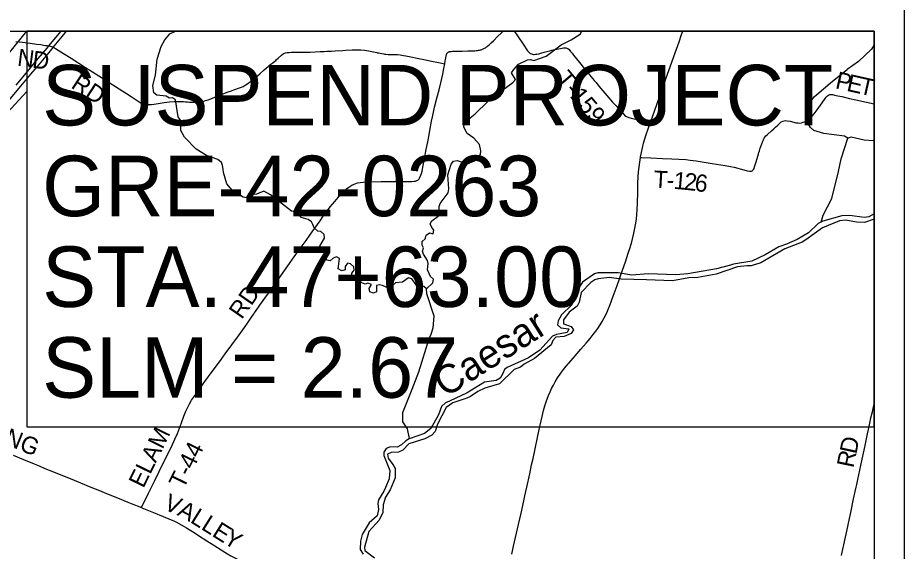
# Model space of a CAD drawing. Extents: x -19.5 to 44.1, y 0 to 22.
# Drawn here: x 6.569 to 9.5, y 16.078 to 17.841 of the extents above; entities that cross this region are included whole.
import ezdxf

# ---------------------------------------------------------------- set-up
doc = ezdxf.new("R2010")
doc.units = 0
for name, color, linetype in [('GM_X_County_Road', 7, 'Continuous'), ('GM_X_County_Road_Text', 7, 'Continuous'), ('GM_X_Major_River', 7, 'Continuous'), ('GM_X_Major_River_Text', 7, 'Continuous'), ('GM_X_Minor_River', 7, 'Continuous'), ('GM_X_State_Route', 7, 'Continuous'), ('GM_X_Township_Road', 7, 'Continuous'), ('GM_X_Township_Road_Text', 7, 'Continuous'), ('GM_X_US_Route', 7, 'Continuous'), ('SH_Data', 7, 'Continuous'), ('SH_Masking', 7, 'Continuous'), ('SH_Text', 7, 'Continuous')]:
    doc.layers.add(name, color=color, linetype=linetype)

msp = doc.modelspace()

# ---------------------------------------------------------------- linework, layer by layer
at = {"layer": 'GM_X_County_Road'}
for points in [[(9.292, 16.0637), (9.2979, 16.0906), (9.2999, 16.0997), (9.3053, 16.1246), (9.3096, 16.1447), (9.3185, 16.186), (9.3228, 16.2066), (9.3325, 16.2516), (9.3378, 16.2752), (9.3409, 16.2898), (9.3427, 16.2983), (9.3462, 16.3147), (9.3496, 16.3305), (9.3531, 16.3462), (9.3611, 16.382), (9.3652, 16.4027), (9.3704, 16.4277), (9.3787, 16.4665), (9.3816, 16.4805), (9.3862, 16.5017), (9.3899, 16.5186), (9.3945, 16.5393), (9.3981, 16.5548), (9.4, 16.5632)], [(6.5534, 16.3958), (6.5878, 16.3814), (6.6229, 16.3671), (6.6395, 16.3601), (6.659, 16.352), (6.6815, 16.343), (6.6948, 16.3377), (6.731, 16.3228), (6.7552, 16.3132), (6.8103, 16.2903), (6.8396, 16.2784), (6.862, 16.2692), (6.904, 16.2522), (6.927, 16.2429), (6.9316, 16.2411), (6.9333, 16.2404), (6.9441, 16.236), (6.978, 16.2221)], [(6.978, 16.2221), (6.9792, 16.2216), (7.0178, 16.206), (7.0504, 16.1923), (7.0871, 16.1771), (7.0944, 16.1737), (7.1016, 16.1701), (7.1118, 16.1643), (7.1266, 16.1552), (7.1356, 16.1497), (7.1519, 16.1395), (7.1672, 16.1299), (7.1938, 16.1128), (7.2086, 16.1037), (7.2291, 16.0908), (7.2542, 16.0747), (7.2622, 16.0698), (7.2741, 16.0631), (7.2867, 16.0563), (7.2996, 16.05), (7.311, 16.045), (7.3237, 16.0398), (7.3281, 16.0383)]]:
    msp.add_lwpolyline(points, dxfattribs=at)
at = {"layer": 'GM_X_Major_River'}
for points in [[(9.4, 17.1929), (9.3828, 17.183), (9.3672, 17.1807), (9.3202, 17.1875), (9.294, 17.1869), (9.2308, 17.169), (9.2158, 17.161), (9.1836, 17.1306), (9.1462, 17.1083), (9.1105, 17.0931), (9.0852, 17.0838), (9.0401, 17.0579), (8.9959, 17.0372), (8.9352, 17.0269), (8.9257, 17.024), (8.8794, 17.0114), (8.7843, 16.995), (8.7451, 16.9913), (8.6528, 16.9946), (8.5995, 16.9905), (8.554, 16.998), (8.4871, 16.9984)], [(9.4, 17.1756), (9.3684, 17.1647), (9.3418, 17.1661), (9.3066, 17.1722), (9.2864, 17.1696), (9.2296, 17.1474), (9.1751, 17.1076), (9.1619, 17.0991), (9.1048, 17.0773), (9.0262, 17.0308), (8.9933, 17.0217), (8.9792, 17.0213), (8.9491, 17.0182), (8.8782, 16.994), (8.8175, 16.9832), (8.7874, 16.9812), (8.734, 16.9722), (8.6478, 16.9746), (8.5638, 16.9777), (8.524, 16.9828), (8.4882, 16.9787)], [(8.4871, 16.9984), (8.4764, 16.9945), (8.4362, 16.9669), (8.411, 16.9295), (8.4059, 16.9057), (8.4007, 16.8921), (8.3665, 16.8598), (8.3561, 16.8395), (8.3535, 16.8263), (8.3647, 16.8165), (8.3905, 16.8129), (8.3853, 16.8005), (8.3502, 16.7948), (8.3367, 16.7894), (8.295, 16.7425), (8.2575, 16.7168), (8.1876, 16.6849), (8.1779, 16.6787), (8.1731, 16.6659), (8.164, 16.6505), (8.1509, 16.6428), (8.112, 16.6369), (8.0545, 16.6013), (7.9969, 16.5738), (7.9838, 16.5684), (7.9702, 16.5569), (7.9605, 16.529), (7.9351, 16.4832), (7.9142, 16.4674), (7.8628, 16.4499), (7.8517, 16.443), (7.838, 16.4292), (7.8234, 16.4219), (7.801, 16.4236), (7.7876, 16.4171), (7.7789, 16.4051), (7.7794, 16.3941), (7.7996, 16.3446), (7.7967, 16.3177), (7.785, 16.2883), (7.7794, 16.2762), (7.7613, 16.2482), (7.7591, 16.2353), (7.7616, 16.2158), (7.7574, 16.1947), (7.7306, 16.1721), (7.7081, 16.1338), (7.7026, 16.1112), (7.7016, 16.0842), (7.7107, 16.0684)], [(8.4882, 16.9787), (8.4767, 16.9751), (8.4643, 16.9659), (8.432, 16.9332), (8.4252, 16.901), (8.4185, 16.8883), (8.3925, 16.868), (8.3737, 16.8433), (8.373, 16.8293), (8.399, 16.8211), (8.4068, 16.8099), (8.3989, 16.7975), (8.3755, 16.7882), (8.3484, 16.7858), (8.3379, 16.7746), (8.3326, 16.7603), (8.2772, 16.7152), (8.2437, 16.6962), (8.2317, 16.6866), (8.2099, 16.6787), (8.1616, 16.6308), (8.1134, 16.6167), (8.09, 16.6058), (8.0664, 16.5897), (8.0534, 16.5843), (8.007, 16.5682), (7.9854, 16.5531), (7.9567, 16.4983), (7.9486, 16.4742), (7.9376, 16.4615), (7.9145, 16.4491), (7.8625, 16.4328), (7.8418, 16.412), (7.8284, 16.4059), (7.8033, 16.4045), (7.7913, 16.3984), (7.7933, 16.3858), (7.8096, 16.3649), (7.8165, 16.351), (7.8165, 16.3202), (7.8004, 16.2807), (7.7846, 16.2564), (7.7772, 16.2311), (7.7766, 16.206), (7.7639, 16.1804), (7.73, 16.1436), (7.7151, 16.0919), (7.7163, 16.0801), (7.7488, 16.0557)]]:
    msp.add_lwpolyline(points, dxfattribs=at)
at = {"layer": 'GM_X_Minor_River'}
for points in [[(7.0298, 17.7049), (7.0436, 17.7467), (7.055, 17.7678), (7.0721, 17.7884), (7.0904, 17.7973)], [(8.2246, 17.6874), (8.2541, 17.7017), (8.2644, 17.7034), (8.2753, 17.7005), (8.3162, 17.7147), (8.3658, 17.7518), (8.3988, 17.7683), (8.4283, 17.7875), (8.4345, 17.7973)], [(9.4, 17.7521), (9.3919, 17.7375), (9.3483, 17.6965), (9.311, 17.6705)], [(7.9208, 16.9457), (7.9111, 16.9535), (7.8865, 16.9586), (7.8722, 16.9787), (7.8608, 16.9816), (7.8408, 16.9669), (7.8184, 16.9648), (7.7967, 16.9463), (7.7753, 16.9567), (7.7647, 16.9588), (7.7552, 16.956), (7.7547, 16.9351), (7.7452, 16.9308), (7.7335, 16.9356), (7.7311, 16.9463), (7.7382, 16.9598), (7.7269, 16.9643), (7.7173, 16.9603), (7.7068, 16.9647), (7.6957, 16.9764), (7.6739, 16.9868), (7.6737, 16.9974), (7.6808, 17.0071), (7.6802, 17.0178), (7.6694, 17.0275), (7.6596, 17.03), (7.6514, 17.0188), (7.652, 17.0086), (7.6405, 17.0046), (7.6281, 17.011), (7.633, 17.0451), (7.6229, 17.051), (7.6118, 17.0467), (7.6017, 17.0375), (7.5915, 17.0396), (7.5884, 17.0503), (7.5985, 17.0618), (7.6002, 17.0717), (7.5896, 17.0738), (7.5747, 17.0689), (7.5649, 17.071), (7.5647, 17.0809), (7.5832, 17.1127), (7.582, 17.1245), (7.5716, 17.135), (7.561, 17.136), (7.5494, 17.1466), (7.5447, 17.1577), (7.5408, 17.1673), (7.5292, 17.1748), (7.5065, 17.1814), (7.4849, 17.1994), (7.4736, 17.2023), (7.4049, 17.2559), (7.3824, 17.2678), (7.3579, 17.2578), (7.3473, 17.2573), (7.3258, 17.246), (7.3141, 17.2482), (7.2778, 17.2714), (7.26, 17.2927), (7.249, 17.3295), (7.2485, 17.3409), (7.2465, 17.3527), (7.2425, 17.3634), (7.2302, 17.3724), (7.1929, 17.3858), (7.1592, 17.4064), (7.1206, 17.4468), (7.1078, 17.4684), (7.1074, 17.5026), (7.0993, 17.5142), (7.0906, 17.5698), (7.0809, 17.5769), (7.071, 17.5752), (7.0594, 17.5823), (7.0287, 17.5853), (7.019, 17.5935), (7.0154, 17.6172), (7.0248, 17.6511), (7.0298, 17.7049)], [(7.8648, 16.4506), (7.8574, 16.4826), (7.8427, 16.5053), (7.8426, 16.5369), (7.8735, 16.6132), (7.8952, 16.6705), (7.929, 16.7817), (7.9358, 16.796), (7.9423, 16.8164), (7.9458, 16.8551), (7.922, 16.9293), (7.9208, 16.9457), (7.9409, 16.9653), (7.9439, 16.977), (7.9334, 16.9864), (7.924, 17.0079), (7.9256, 17.0291), (7.9236, 17.0394), (7.9107, 17.0599), (7.9075, 17.0702), (7.91, 17.0804), (7.9057, 17.09), (7.9063, 17.1021), (7.9163, 17.1103), (7.9193, 17.1231), (7.9301, 17.1308), (7.9421, 17.1271), (7.945, 17.1392), (7.9365, 17.1497), (7.933, 17.16), (7.9381, 17.1698), (7.9586, 17.1852), (7.9637, 17.1965), (7.9627, 17.2174), (7.9655, 17.2272), (7.9921, 17.2631), (7.9943, 17.276), (7.9907, 17.3216), (8.0017, 17.3578), (8.0099, 17.3675), (8.0217, 17.3691), (8.0556, 17.3585), (8.0786, 17.3686), (8.0898, 17.3767), (8.0992, 17.3897), (8.1005, 17.4015), (8.0957, 17.4221), (8.0768, 17.4431), (8.0551, 17.4588), (8.0434, 17.4796), (8.0455, 17.4901), (8.0541, 17.5017), (8.0819, 17.5235), (8.0908, 17.5331), (8.1358, 17.5758), (8.2059, 17.6273), (8.2145, 17.6374), (8.2013, 17.6597), (8.2091, 17.6698), (8.2246, 17.6874)], [(9.3139, 17.4434), (9.3029, 17.4497), (9.2344, 17.4585), (9.2013, 17.4688), (9.1905, 17.4785), (9.1839, 17.4901), (9.1821, 17.5137), (9.1947, 17.57), (9.2029, 17.5812), (9.2628, 17.6314), (9.311, 17.6705)], [(9.2257, 17.1662), (9.2321, 17.1884), (9.2602, 17.244), (9.2826, 17.3331), (9.2911, 17.3755), (9.3138, 17.4433), (9.3242, 17.4476), (9.3676, 17.4375), (9.3971, 17.4357), (9.4, 17.4367)]]:
    msp.add_lwpolyline(points, dxfattribs=at)
at = {"layer": 'GM_X_State_Route'}
for points in [[(8.6623, 17.4986), (8.6691, 17.5175), (8.6953, 17.592), (8.7042, 17.6178), (8.7128, 17.6424), (8.7214, 17.667), (8.7423, 17.7248), (8.7557, 17.7622), (8.7639, 17.7856), (8.7676, 17.7973)], [(8.2952, 16.4899), (8.2962, 16.4946), (8.3029, 16.5237), (8.3078, 16.543), (8.3122, 16.5585), (8.3165, 16.5722), (8.3205, 16.584), (8.3241, 16.5933), (8.329, 16.6047), (8.3342, 16.616), (8.3399, 16.6272), (8.3456, 16.6375), (8.3538, 16.6507), (8.362, 16.6633), (8.367, 16.6704), (8.3731, 16.6783), (8.3825, 16.6899), (8.406, 16.7173), (8.431, 16.7458), (8.4486, 16.7658), (8.4618, 16.7815), (8.4719, 16.7941), (8.4801, 16.805), (8.4868, 16.8146), (8.4943, 16.826), (8.5014, 16.8377), (8.508, 16.8496), (8.514, 16.8612), (8.5187, 16.8713), (8.5224, 16.8798), (8.5278, 16.8937), (8.5379, 16.9211), (8.5503, 16.9562), (8.5592, 16.9814), (8.5684, 17.0072), (8.5779, 17.0348), (8.5876, 17.0629), (8.5937, 17.0819), (8.5992, 17.1009), (8.6029, 17.1153), (8.6061, 17.1292), (8.6095, 17.1463), (8.6123, 17.1628), (8.6142, 17.1769), (8.6157, 17.1911), (8.6168, 17.2066), (8.6178, 17.2289), (8.6189, 17.2649), (8.6196, 17.2947), (8.6205, 17.3153), (8.6218, 17.332), (8.6233, 17.3475), (8.6255, 17.3641), (8.6279, 17.3798), (8.6281, 17.3814), (8.6308, 17.3954), (8.6343, 17.4112), (8.6381, 17.4263), (8.6422, 17.4407), (8.647, 17.4555), (8.6546, 17.4772), (8.6613, 17.4957), (8.6623, 17.4986)], [(8.2027, 16.068), (8.2086, 16.0947), (8.2212, 16.1517), (8.2245, 16.1669), (8.2331, 16.2044), (8.2422, 16.245), (8.2458, 16.2614), (8.2521, 16.2899), (8.2616, 16.3336), (8.268, 16.3634), (8.2726, 16.3847), (8.2798, 16.4168), (8.2878, 16.4538), (8.2921, 16.4751), (8.2952, 16.4899)]]:
    msp.add_lwpolyline(points, dxfattribs=at)
at = {"layer": 'GM_X_Township_Road'}
for points in [[(7.9806, 17.6891), (7.9824, 17.6992), (7.9839, 17.7073), (7.9857, 17.7164), (7.9861, 17.7182), (7.9863, 17.7191), (7.9867, 17.7203), (7.9871, 17.7213), (7.9875, 17.7224), (7.9881, 17.7234), (7.9888, 17.7244), (7.9894, 17.725), (7.9899, 17.7256), (7.9911, 17.7266), (7.9921, 17.7275), (7.9933, 17.7282), (7.9944, 17.7287), (7.9953, 17.7291), (7.9964, 17.7294), (7.998, 17.7297), (8, 17.7299), (8.0025, 17.7301), (8.0069, 17.7303), (8.0113, 17.7305), (8.0187, 17.7307), (8.0314, 17.7311), (8.0386, 17.7313), (8.0566, 17.7316), (8.0752, 17.7322), (8.0804, 17.7324), (8.0851, 17.7327), (8.0891, 17.7331), (8.0924, 17.7336), (8.0954, 17.7342), (8.0985, 17.7349), (8.1013, 17.7357), (8.1031, 17.7363), (8.1058, 17.7372), (8.1083, 17.7383), (8.1123, 17.7403), (8.1158, 17.7423), (8.1191, 17.7447), (8.1222, 17.7471), (8.1273, 17.7515), (8.1346, 17.7582), (8.1426, 17.766), (8.1555, 17.779), (8.168, 17.7916), (8.1738, 17.7973)], [(8.21, 17.7973), (8.2166, 17.7878), (8.226, 17.7747), (8.2358, 17.7605), (8.2446, 17.7478), (8.2503, 17.739), (8.2547, 17.7321), (8.2577, 17.7281), (8.2605, 17.7255), (8.2635, 17.7232), (8.2672, 17.7217), (8.271, 17.7207), (8.2745, 17.7202), (8.2764, 17.7202), (8.2808, 17.7206), (8.2856, 17.7214), (8.2921, 17.7224), (8.2983, 17.7238), (8.3098, 17.7271), (8.3181, 17.7296), (8.328, 17.7322), (8.3353, 17.734), (8.3433, 17.7358), (8.3512, 17.7374), (8.3567, 17.7385), (8.364, 17.7402), (8.3682, 17.7411), (8.3736, 17.7419), (8.3784, 17.7423), (8.3813, 17.742), (8.3846, 17.7411), (8.3872, 17.7399), (8.3918, 17.7361), (8.397, 17.7301), (8.4019, 17.7238), (8.4065, 17.7179), (8.4159, 17.7057), (8.4259, 17.6931), (8.4429, 17.6727), (8.4466, 17.6679), (8.4558, 17.6566), (8.4594, 17.6524), (8.465, 17.6458), (8.4698, 17.6401), (8.4751, 17.6342), (8.4811, 17.6273), (8.4866, 17.6201), (8.4917, 17.6139), (8.4962, 17.6085), (8.5105, 17.5918), (8.517, 17.5839), (8.5359, 17.5626), (8.5409, 17.5571), (8.5472, 17.5503), (8.5546, 17.5421), (8.5695, 17.5255), (8.5754, 17.5198), (8.5799, 17.5164), (8.5843, 17.5139), (8.5896, 17.5117), (8.5968, 17.5096), (8.6217, 17.5041), (8.6466, 17.499), (8.6581, 17.4965), (8.6613, 17.4957)], [(6.5625, 17.7628), (6.5851, 17.7601), (6.6101, 17.757), (6.6307, 17.7544), (6.6451, 17.7525), (6.6544, 17.7512), (6.6613, 17.7501), (6.6659, 17.7494), (6.672, 17.7485)], [(6.672, 17.7485), (6.6765, 17.7476), (6.6801, 17.7467), (6.6837, 17.7453), (6.6869, 17.7437)], [(6.6869, 17.7437), (6.6938, 17.7397), (6.7022, 17.7345), (6.7206, 17.7228), (6.7453, 17.7072), (6.7935, 17.6765), (6.8167, 17.662), (6.846, 17.6434), (6.8718, 17.6272), (6.9042, 17.6064), (6.9288, 17.5906), (6.9438, 17.5807), (6.9572, 17.5717), (6.9667, 17.5658), (6.9742, 17.5612), (6.9797, 17.5582), (6.9843, 17.5564), (6.9889, 17.555), (6.9922, 17.5545), (6.996, 17.5544), (7.0036, 17.5543), (7.0111, 17.5548), (7.0265, 17.5568), (7.0461, 17.5598), (7.0529, 17.5609), (7.0707, 17.5631), (7.0867, 17.5646), (7.0962, 17.5649), (7.1028, 17.5648), (7.1109, 17.5646), (7.117, 17.5643), (7.1237, 17.5639), (7.1299, 17.5633), (7.1367, 17.5628), (7.1479, 17.5623), (7.1559, 17.562), (7.1597, 17.562), (7.1671, 17.5625), (7.1713, 17.5631), (7.1811, 17.565), (7.1896, 17.5673), (7.199, 17.5705), (7.2077, 17.5738), (7.2205, 17.5786), (7.2313, 17.5829)], [(7.2313, 17.5829), (7.232, 17.5832), (7.248, 17.5899), (7.2538, 17.5919), (7.2619, 17.5949), (7.2677, 17.5971), (7.2729, 17.599), (7.284, 17.603), (7.3056, 17.6109), (7.3143, 17.6146), (7.321, 17.6181), (7.3263, 17.6214), (7.3314, 17.6249), (7.3374, 17.6295), (7.3405, 17.6321), (7.3469, 17.6374), (7.3497, 17.6398), (7.3613, 17.6498), (7.369, 17.6562), (7.3841, 17.6691), (7.3971, 17.6804), (7.403, 17.6852), (7.4119, 17.6921), (7.4192, 17.698), (7.422, 17.7004), (7.4249, 17.7028), (7.4306, 17.7077), (7.4416, 17.7177), (7.4469, 17.7218), (7.4505, 17.7239), (7.4543, 17.7254), (7.4596, 17.7265), (7.4626, 17.7269), (7.4662, 17.7269), (7.4744, 17.727), (7.4872, 17.7272), (7.4978, 17.7272), (7.5109, 17.7274), (7.5261, 17.7278), (7.5363, 17.728), (7.5523, 17.7287), (7.5685, 17.7293), (7.5826, 17.7301), (7.5914, 17.7306), (7.6063, 17.7312), (7.6187, 17.7318), (7.6435, 17.7333), (7.6534, 17.7338), (7.6745, 17.7349), (7.685, 17.7352), (7.6893, 17.7354), (7.6985, 17.7353), (7.7034, 17.735), (7.7151, 17.7337), (7.7291, 17.7314), (7.7395, 17.7296), (7.7511, 17.7274), (7.7559, 17.7264), (7.759, 17.7257), (7.7632, 17.7248), (7.7723, 17.7229), (7.7796, 17.7215), (7.7827, 17.7212), (7.7864, 17.7207), (7.7938, 17.7201), (7.8031, 17.7199), (7.8056, 17.72), (7.8093, 17.7202), (7.8167, 17.7202), (7.8247, 17.7198), (7.8332, 17.7186), (7.8442, 17.7166), (7.8521, 17.7151), (7.8636, 17.7128), (7.8685, 17.7118), (7.8897, 17.7075), (7.9225, 17.701), (7.9367, 17.6982), (7.9597, 17.6933), (7.9806, 17.6891)], [(6.978, 16.2221), (6.9793, 16.2247), (7.0011, 16.2695), (7.0224, 16.3123), (7.0365, 16.3414), (7.0458, 16.3604), (7.0771, 16.4232), (7.0889, 16.4479), (7.0975, 16.4671), (7.1044, 16.4844), (7.111, 16.5025), (7.1184, 16.5243), (7.125, 16.5411), (7.1309, 16.5542), (7.1371, 16.5657), (7.144, 16.5769), (7.1535, 16.5907), (7.1881, 16.6386), (7.2155, 16.6763), (7.2393, 16.7089), (7.255, 16.7305), (7.2767, 16.7601), (7.2889, 16.7765), (7.2929, 16.7821), (7.3182, 16.8174), (7.3308, 16.8353), (7.3395, 16.8481), (7.3496, 16.8622), (7.3512, 16.8648), (7.3519, 16.8658), (7.3552, 16.8701), (7.3699, 16.8909), (7.3865, 16.9141), (7.4048, 16.94), (7.4198, 16.9613), (7.427, 16.9715), (7.4388, 16.9882), (7.4567, 17.0136), (7.4672, 17.029), (7.4797, 17.0468), (7.5057, 17.0825), (7.5223, 17.105), (7.5352, 17.1232), (7.5451, 17.1375), (7.5509, 17.1456), (7.5685, 17.1704), (7.579, 17.185), (7.5883, 17.1982), (7.5962, 17.2091), (7.6016, 17.2162), (7.6169, 17.2342), (7.6281, 17.2475), (7.6342, 17.2546), (7.6418, 17.2628), (7.6494, 17.2701), (7.6557, 17.2753), (7.6638, 17.2811), (7.6738, 17.2875), (7.681, 17.2914), (7.6868, 17.2938), (7.6922, 17.2955), (7.7009, 17.2971), (7.7114, 17.2982), (7.7232, 17.2989), (7.7375, 17.2994), (7.7704, 17.3001), (7.8058, 17.3005), (7.8226, 17.3004), (7.8524, 17.3), (7.8722, 17.3001), (7.8796, 17.3007), (7.8843, 17.3016), (7.8883, 17.3029), (7.8915, 17.3046), (7.8942, 17.3069), (7.8961, 17.3091), (7.8976, 17.3115), (7.9015, 17.3205), (7.9036, 17.3263), (7.9057, 17.3346), (7.9098, 17.3534), (7.9138, 17.3742), (7.9186, 17.3998), (7.9256, 17.437), (7.9289, 17.4541), (7.9315, 17.4681), (7.9374, 17.4992), (7.9414, 17.5187), (7.9471, 17.546), (7.9545, 17.5756), (7.9619, 17.6026), (7.9677, 17.6261), (7.974, 17.6546), (7.9779, 17.6741), (7.9806, 17.6891)], [(8.6279, 17.3798), (8.6321, 17.3796), (8.6619, 17.3781), (8.701, 17.3764), (8.732, 17.3749), (8.7773, 17.3724), (8.7921, 17.3711), (8.8118, 17.3684), (8.8381, 17.3641), (8.8651, 17.3599), (8.9081, 17.3529), (8.9251, 17.3497), (8.9372, 17.3469), (8.9691, 17.3385), (8.9811, 17.3354), (8.9879, 17.3339), (8.9912, 17.3337), (8.9944, 17.3344), (8.9974, 17.3358), (8.9995, 17.3375), (9.0016, 17.34), (9.0035, 17.3434), (9.0052, 17.3482), (9.01, 17.3653), (9.0134, 17.3759), (9.0178, 17.391), (9.0194, 17.3957), (9.0214, 17.4016), (9.0241, 17.4098), (9.029, 17.4245), (9.0321, 17.4333), (9.0343, 17.4383), (9.0356, 17.4407), (9.0373, 17.4436), (9.0402, 17.4475), (9.0426, 17.4505), (9.048, 17.4557), (9.0614, 17.4676), (9.0684, 17.4739), (9.0748, 17.4795), (9.0816, 17.4862), (9.0852, 17.4896), (9.0879, 17.4923), (9.0933, 17.497), (9.0985, 17.5), (9.1031, 17.5011), (9.1073, 17.5012), (9.1127, 17.5008), (9.1225, 17.499), (9.1352, 17.4961), (9.1419, 17.4945), (9.1481, 17.4935), (9.1551, 17.4933), (9.1607, 17.4942), (9.1661, 17.4958), (9.1708, 17.4977), (9.1743, 17.4992), (9.1827, 17.5035), (9.1883, 17.5076), (9.1926, 17.5114), (9.1971, 17.5166), (9.2024, 17.5236), (9.2118, 17.5367), (9.2228, 17.5526), (9.2286, 17.5606), (9.238, 17.5745), (9.2417, 17.5793), (9.2457, 17.583), (9.2497, 17.5856), (9.2542, 17.5871), (9.2589, 17.5875), (9.2637, 17.5871), (9.2698, 17.5859), (9.28, 17.5835), (9.2933, 17.5805), (9.319, 17.5748), (9.3397, 17.5704), (9.3748, 17.5625), (9.4, 17.5569)]]:
    msp.add_lwpolyline(points, dxfattribs=at)
at = {"layer": 'GM_X_US_Route'}
for points in [[(6.4651, 17.4785), (6.4679, 17.4819), (6.4926, 17.5115), (6.5561, 17.5872), (6.5847, 17.6216), (6.6126, 17.655), (6.6405, 17.6883), (6.6625, 17.7145), (6.6869, 17.7437), (6.69, 17.7474), (6.7115, 17.7739), (6.7301, 17.7965), (6.7308, 17.7973)], [(6.5635, 17.6184), (6.5814, 17.6399), (6.6013, 17.6637), (6.6217, 17.688), (6.6368, 17.7062), (6.6658, 17.741), (6.672, 17.7485), (6.6897, 17.7697), (6.7126, 17.7973)]]:
    msp.add_lwpolyline(points, dxfattribs=at)
at = {"layer": 'SH_Data'}
for p, q in [((9.5, 21.3473), (9.5, 14.3473)), ((2.6, 17.7973), (9.4, 17.7973)), ((9.4, 17.7973), (9.4, 14.4473))]:
    msp.add_line(p, q, dxfattribs=at)
at = {"layer": 'SH_Masking'}
msp.add_lwpolyline([(6.5995, 16.4893), (9.4, 16.4893), (9.4, 17.7973), (6.5995, 17.7973)], close=True, dxfattribs=at)
at = {"layer": 'SH_Text'}
for points in [[(6.5995, 17.5973), (5.2798, 16.1676), (6.5995, 17.7973)], [(6.5995, 16.4893), (9.4, 16.4893), (9.4, 17.7973), (6.5995, 17.7973)]]:
    msp.add_lwpolyline(points, close=True, dxfattribs=at)

# ---------------------------------------------------------------- texts
at = {"layer": 'GM_X_County_Road_Text'}
for s, height, rotation, p in [('SPRING', 0.05682, 337.6606, (6.3564, 16.5016)), ('D', 0.0568, 77.7248, (9.3412, 16.3968)), ('R', 0.0568, 78.3357, (9.3318, 16.3513)), ('V', 0.0568, 336.1566, (7.0485, 16.2181)), ('A', 0.0568, 331.8073, (7.0932, 16.1984)), ('L', 0.0568, 328.0087, (7.1364, 16.1753)), ('L', 0.0568, 327.8874, (7.1724, 16.1528)), ('E', 0.0568, 327.9215, (7.2084, 16.1301)), ('Y', 0.0568, 328.7181, (7.2452, 16.1071))]:
    msp.add_text(s, height=height, rotation=rotation, dxfattribs=at).set_placement(p)
at = {"layer": 'GM_X_Major_River_Text'}
msp.add_text('Caesar', height=0.09469, rotation=32.5146, dxfattribs=at).set_placement((7.9828, 16.5839))
at = {"layer": 'GM_X_Township_Road_Text'}
for s, height, rotation, p in [('N', 0.0568, 352.7205, (6.5655, 17.6828)), ('D', 0.0568, 352.7471, (6.6151, 17.6764)), ('RD', 0.05682, 326.8524, (6.7421, 17.6118)), ('T-159', 0.05682, 310.0704, (8.3458, 17.6367)), ('P', 0.0568, 347.2903, (9.2694, 17.6088)), ('E', 0.0568, 347.2881, (9.3068, 17.6003)), ('T', 0.0568, 347.2902, (9.3482, 17.591)), ('T', 0.0568, 356.6381, (8.6703, 17.28)), ('1', 0.0568, 355.191, (8.7356, 17.276)), ('2', 0.0568, 353.9311, (8.7702, 17.2731)), ('6', 0.0568, 352.6529, (8.8047, 17.2694)), ('-', 0.0568, 356.2269, (8.7126, 17.2775)), ('RD', 0.05682, 55.0047, (7.3096, 16.8418)), ('ELAM', 0.05682, 63.8526, (6.9843, 16.2839)), ('T-44', 0.05682, 63.9042, (7.1173, 16.281))]:
    msp.add_text(s, height=height, rotation=rotation, dxfattribs=at).set_placement(p)
at = {"layer": 'SH_Text'}
for s, p in [('SUSPEND PROJECT', (6.6499, 17.4854)), ('GRE-42-0263', (6.6499, 17.1854)), ('STA. 47+63.00', (6.6499, 16.8854)), ('SLM = 2.67', (6.6499, 16.5854))]:
    msp.add_text(s, height=0.2, rotation=360, dxfattribs=at).set_placement(p)

doc.saveas('drawing.dxf')
